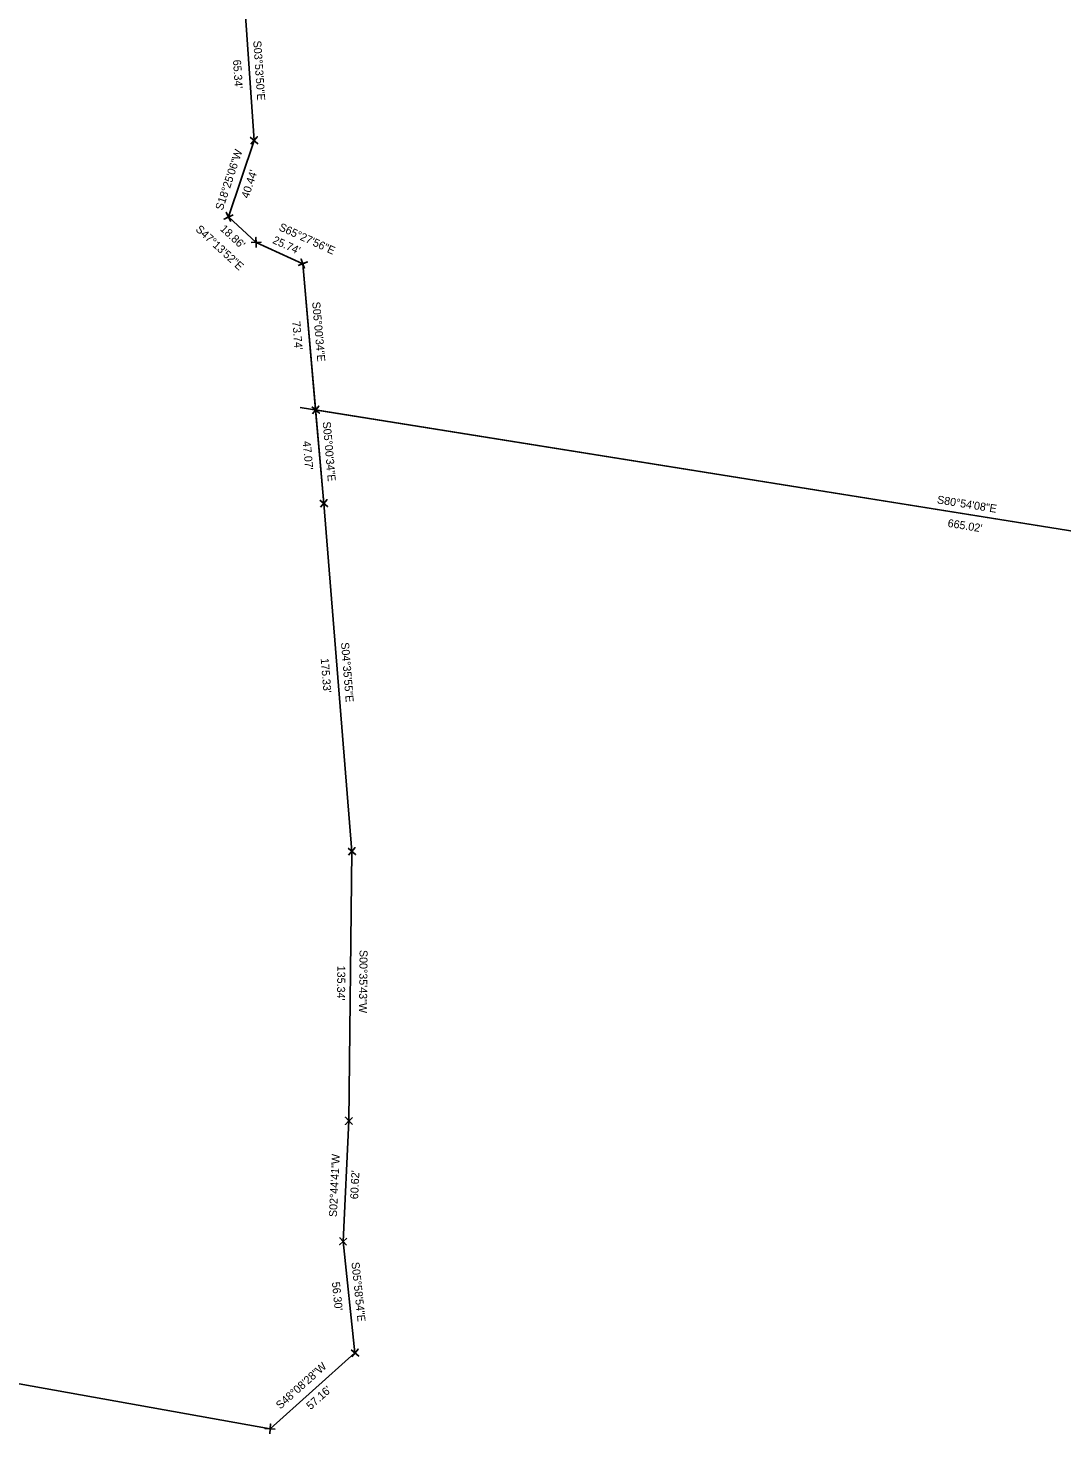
# Model space of a CAD drawing. Extents: x 1107874 to 1110849, y 645477 to 647181.
# Drawn here: x 1109049 to 1109568, y 645477 to 646183 of the extents above; entities that cross this region are included whole.
import ezdxf

# ---------------------------------------------------------------- set-up
doc = ezdxf.new("R2010")
doc.units = 0
for name, color, linetype in [('Exist Property Corner CELL', 7, 'Continuous'), ('Exist Property Line', 7, 'Continuous'), ('Exist Property Text', 7, 'Continuous')]:
    doc.layers.add(name, color=color, linetype=linetype)

msp = doc.modelspace()

# ---------------------------------------------------------------- linework, layer by layer
at = {"layer": 'Exist Property Corner CELL'}
for p, q in [((1109162.44, 646126.61), (1109162.44, 646126.61)), ((1109149.66, 646088.23), (1109149.66, 646088.23)), ((1109163.51, 646075.43), (1109163.51, 646075.43)), ((1109186.92, 646064.74), (1109186.92, 646064.74)), ((1109193.36, 645991.28), (1109193.36, 645991.28)), ((1109197.47, 645944.39), (1109197.47, 645944.39)), ((1109211.53, 645769.62), (1109211.53, 645769.62)), ((1109210.12, 645634.29), (1109210.12, 645634.29)), ((1109207.22, 645573.74), (1109207.22, 645573.74)), ((1109213.09, 645517.75), (1109213.09, 645517.75)), ((1109170.51, 645479.6), (1109170.51, 645479.6))]:
    msp.add_line(p, q, dxfattribs=at)
for points in [[(1109160.56, 646128.25), (1109164.32, 646124.96), (1109162.44, 646126.61), (1109164.09, 646128.49), (1109160.8, 646124.72)], [(1109150.78, 646086), (1109148.54, 646090.47), (1109149.66, 646088.23), (1109147.43, 646087.12), (1109151.9, 646089.35)], [(1109161.01, 646075.33), (1109166.01, 646075.52), (1109163.51, 646075.43), (1109163.41, 646077.92), (1109163.6, 646072.93)], [(1109184.58, 646063.87), (1109189.27, 646065.61), (1109186.92, 646064.74), (1109186.05, 646067.08), (1109187.8, 646062.4)], [(1109191.45, 645992.89), (1109195.28, 645989.67), (1109193.36, 645991.28), (1109194.97, 645993.2), (1109191.76, 645989.37)], [(1109195.57, 645946.01), (1109199.38, 645942.77), (1109197.47, 645944.39), (1109199.09, 645946.29), (1109195.85, 645942.49)], [(1109209.63, 645771.25), (1109213.43, 645768), (1109211.53, 645769.62), (1109213.15, 645771.53), (1109209.91, 645767.72)], [(1109211.87, 645632.5), (1109208.37, 645636.08), (1109210.12, 645634.29), (1109208.34, 645632.54), (1109211.91, 645636.04)], [(1109208.9, 645571.89), (1109205.54, 645575.59), (1109207.22, 645573.74), (1109205.37, 645572.06), (1109209.07, 645575.42)], [(1109211.15, 645519.32), (1109215.03, 645516.17), (1109213.09, 645517.75), (1109214.66, 645519.69), (1109211.51, 645515.81)], [(1109170.38, 645477.11), (1109170.65, 645482.1), (1109170.51, 645479.6), (1109168.02, 645479.74), (1109173.01, 645479.47)]]:
    msp.add_lwpolyline(points, dxfattribs=at)
at = {"layer": 'Exist Property Line'}
for p, q in [((1109158, 646191.79), (1109162.44, 646126.61)), ((1109162.44, 646126.61), (1109149.66, 646088.23)), ((1109149.66, 646088.23), (1109163.51, 646075.43)), ((1109163.51, 646075.43), (1109186.92, 646064.74)), ((1109186.92, 646064.74), (1109197.47, 645944.39)), ((1109186.92, 646064.74), (1109193.36, 645991.28)), ((1109185.59, 645992.53), (1109850.02, 645886.13)), ((1109193.36, 645991.28), (1109850.02, 645886.13)), ((1109193.36, 645991.28), (1109197.47, 645944.39)), ((1109197.47, 645944.39), (1109211.53, 645769.62)), ((1109211.53, 645769.62), (1109210.12, 645634.29)), ((1109210.12, 645634.29), (1109207.22, 645573.74)), ((1108536.6, 645593.64), (1109170.51, 645479.6)), ((1109207.22, 645573.74), (1109213.09, 645517.75)), ((1109213.09, 645517.75), (1109170.51, 645479.6))]:
    msp.add_line(p, q, dxfattribs=at)

# ---------------------------------------------------------------- texts
at = {"layer": 'Exist Property Text'}
for s, rotation, p in [('S03°53\'50"E', 273.89714, (1109162.04, 646176.62)), ("65.34'", 273.89714, (1109151.87, 646167.04)), ('S18°25\'06"W', 71.58159, (1109146.68, 646091.23)), ("40.44'", 71.58159, (1109159.69, 646097.25)), ('S47°13\'52"E', 317.23103, (1109132.81, 646081.58)), ("18.86'", 317.23103, (1109145.13, 646081.8)), ('S65°27\'56"E', 335.46548, (1109174.55, 646081.71)), ("25.74'", 335.46548, (1109171.37, 646075.21)), ('S05°00\'34"E', 275.00937, (1109191.63, 646045.46)), ("73.74'", 275.00937, (1109181.64, 646035.69)), ('S05°00\'34"E', 275.00937, (1109196.9, 645985.28)), ("47.07'", 275.00937, (1109186.91, 645975.51)), ('S80°54\'08"E', 350.90226, (1109505.13, 645944.4)), ("665.02'", 350.90226, (1109510.44, 645932.61)), ('S04°35\'55"E', 274.59853, (1109206.11, 645874.44)), ("175.33'", 274.59853, (1109195.91, 645866.49)), ('S00°35\'43"W', 269.40464, (1109215.45, 645720.14)), ("135.34'", 269.40464, (1109204.28, 645712.21)), ('S02°44\'41"W', 87.2552, (1109204.02, 645585.9)), ("60.62'", 87.2552, (1109214.69, 645594.88)), ('S05°58\'54"E', 275.98159, (1109211.34, 645563.21)), ("56.30'", 275.98159, (1109201.52, 645553.27)), ('S48°08\'28"W', 41.85881, (1109175.63, 645489.27)), ("57.16'", 41.85881, (1109190.86, 645488.98))]:
    msp.add_text(s, height=4.02, rotation=rotation, dxfattribs=at).set_placement(p)

doc.saveas('drawing.dxf')
